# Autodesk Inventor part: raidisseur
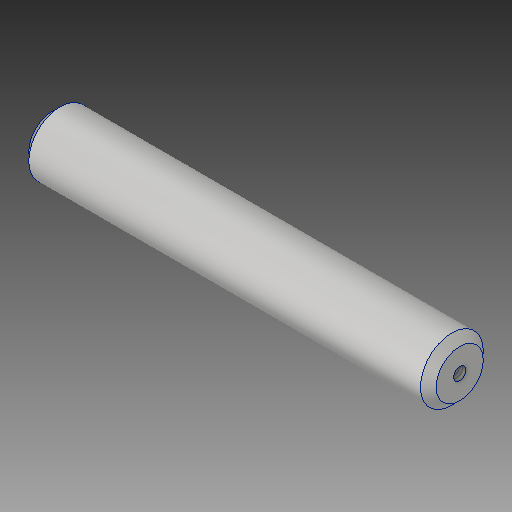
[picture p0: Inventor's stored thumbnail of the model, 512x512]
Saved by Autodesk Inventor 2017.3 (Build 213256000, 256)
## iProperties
Part Number: raidisseur
Material: Aluminium 6061
Document SubType Name: Modeling
Designer: ficho
Density: 2.7 g/cm^3
Appearance: Aluminium - Plat
Mass: 6.90774 g
Surface Area: 14.3434 cm^2
Volume: 2.55842 cm^3
Author: ficho
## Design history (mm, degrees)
sketch "Esquisse1"
  geometry: L1 (0, 0)-(51.852, 0); L2 (51.852, 0)-(51.852, 3); L3 (50.852, 4)-(1, 4); L4 (0, 3)-(0, 0); L5 (0, 3)-(1, 4); L6 (50.852, 4)-(51.852, 3); 2 further points
  constraints: 12 end point, 4 point on line, 2 parallel, 1 horizontal, 1 perpendicular
  dimensions: "d0" = 51.852 distance of point (0, 4) point (51.852, 4); "d1" = 4 distance of point (51.852, 4) L1.end; "d2" = 1 distance of L4.start point (0, 4); "d3" = 1 distance of L3.end point (0, 4) (= d2); "d4" = 1 distance of L3.start point (51.852, 4) (= d2); "d5" = 1 distance of L2.end point (51.852, 4) (= d4)
revolve "Révolution1" sketch "Esquisse1" stored, may be unused: angle "d6" = 90 deg
sketch "Esquisse2"
  geometry: 1 further point
hole "Perçage1" sketch "Esquisse2" at (0, 0) diameter "d7" = 1.567; stored, may be unused: countersink angle "d11" = 90 deg, drill point angle "d13" = 118 deg; dims "d8" = 4, "d9" = 4, "d10" = 2, "d12" = 6.3
sketch "Esquisse3"
  geometry: 1 further point
hole "Perçage2" sketch "Esquisse3" at (0, 0) diameter "d14" = 1.567; stored, may be unused: countersink angle "d18" = 90 deg, drill point angle "d20" = 118 deg; dims "d15" = 4, "d16" = 4, "d17" = 2, "d19" = 6.3
node "Solide1"
